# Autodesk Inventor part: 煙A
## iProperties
Created: 2008-01
Part Number: 煙A
Document SubType Name: Modeling
Designer: t-ikumi
Density: 1 g/cm^3
Author: t-ikumi
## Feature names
1. ロフト2
2. シェル2
3. ロフト3
